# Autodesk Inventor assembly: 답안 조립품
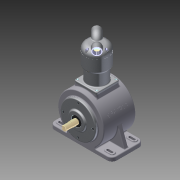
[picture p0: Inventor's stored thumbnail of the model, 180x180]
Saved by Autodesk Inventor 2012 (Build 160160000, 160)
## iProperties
Created: 2015-06
Part Number: 답안 조립품
Document SubType Name: Assembly
Designer: Administrator
Author: Administrator
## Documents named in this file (15)
- C:\Documents and Settings\Administrator\바탕 화면\45065V1004 2 급 한정호\답안 조립품.iam
- C:\Documents and Settings\Administrator\바탕 화면\45065V1004 2 급 한정호\본체.ipt
- C:\Documents and Settings\Administrator\바탕 화면\45065V1004 2 급 한정호\크랭크 서브축.ipt
- C:\Documents and Settings\Administrator\바탕 화면\45065V1004 2 급 한정호\베어링 NA 4902.ipt
- C:\Documents and Settings\Administrator\바탕 화면\45065V1004 2 급 한정호\베어링 6204.ipt
- C:\Documents and Settings\Administrator\바탕 화면\45065V1004 2 급 한정호\커넥팅 로드.ipt
- C:\Documents and Settings\Administrator\바탕 화면\45065V1004 2 급 한정호\메인 크랭크 축-구동부.ipt
- C:\Documents and Settings\Administrator\바탕 화면\45065V1004 2 급 한정호\피스톤 핀.ipt
- C:\Documents and Settings\Administrator\바탕 화면\45065V1004 2 급 한정호\피스톤.ipt
- C:\Documents and Settings\Administrator\바탕 화면\45065V1004 2 급 한정호\실린더헤드.ipt
- C:\Documents and Settings\Administrator\바탕 화면\45065V1004 2 급 한정호\실린더.ipt
- C:\Documents and Settings\Administrator\바탕 화면\45065V1004 2 급 한정호\메인커버.ipt
- C:\Documents and Settings\Administrator\바탕 화면\45065V1004 2 급 한정호\오일실.ipt
- C:\Documents and Settings\Administrator\바탕 화면\45065V1004 2 급 한정호\M5x0.8.ipt
- C:\Documents and Settings\Administrator\바탕 화면\45065V1004 2 급 한정호\M4x0.7.ipt
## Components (10 placed, 4 different names)
1. 피스톤 핀:1
2. 피스톤:1
3. M5x0.8:1
4. M5x0.8:2
5. M5x0.8:3
6. M5x0.8:4
7. M4x0.7:1
8. M4x0.7:2
9. M4x0.7:3
10. M4x0.7:4
